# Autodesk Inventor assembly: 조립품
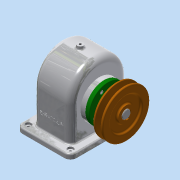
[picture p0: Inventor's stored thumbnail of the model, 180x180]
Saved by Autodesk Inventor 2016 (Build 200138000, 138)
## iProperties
Created: 2018-11
Part Number: 조립품
Material: 일반
Document SubType Name: Assembly
Designer: user
Author: user
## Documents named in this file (14)
- C:\Users\user\Desktop\481111V1005\조립품.iam
- C:\Users\user\Desktop\481111V1005\V-벨트풀리.ipt
- C:\Users\user\Desktop\481111V1005\뒤커버.ipt
- C:\Users\user\Desktop\481111V1005\멈춤나사 M4.ipt
- C:\Users\user\Desktop\481111V1005\베어링 6203.ipt
- C:\Users\user\Desktop\481111V1005\본체.ipt
- C:\Users\user\Desktop\481111V1005\볼트 M4.ipt
- C:\Users\user\Desktop\481111V1005\부시.ipt
- C:\Users\user\Desktop\481111V1005\스퍼기어.ipt
- C:\Users\user\Desktop\481111V1005\앞커버.ipt
- C:\Users\user\Desktop\481111V1005\오일 실 28 40 8.ipt
- C:\Users\user\Desktop\481111V1005\축.ipt
- C:\Users\user\Desktop\481111V1005\키 5x5x18.ipt
- C:\Users\user\Desktop\481111V1005\키 6x6x22.ipt
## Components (1 placed, 1 different names)
1. V-벨트풀리:1
